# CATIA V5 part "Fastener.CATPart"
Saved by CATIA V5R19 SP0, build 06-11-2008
Part number: Fastener
Bounding box of the stored display mesh (mm): x -5 to 5, y -5 to 5, z -48 to 0
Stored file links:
  C:\Users\CADCIM\Desktop\CAT19\c13\Excercise-1\Part & Asm files\Fastener.CATPart
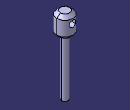
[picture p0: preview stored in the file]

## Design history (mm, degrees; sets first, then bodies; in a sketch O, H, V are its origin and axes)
Body1 (main body)
  Sketch1 on xy-plane, origin (0, 0, 0), H (1, 0, 0), V (0, 1, 0)
    circle A1 centre (0, 0) radius 5
    circle A2 centre (0, 0) radius 2
    radius A2 = 2
    radius A1 = 5
  MultiPad1: profile Sketch1, domains (length 0 / length 48; length 0 / length 13)
  Chamfer1: length 2, angle 45, on 2 edges
  Chamfer2: length 0.508, angle 45, on 1 edge
  Sketch2 on zx-plane, origin (-1.612, 0, 1.612), H (1, 0, 0), V (0, 0, -1)
    point P1 (1.612, 6.35)
    reference intersected line E1 through (1.612, 0) direction (0, 1) from yz-plane
    distance P1 H = 6.35
    coincidence: E1 P1
  Hole1: placed by Sketch2, at (0, 0, -4.738) direction (0, -1, 0), diameter 4, depth 10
